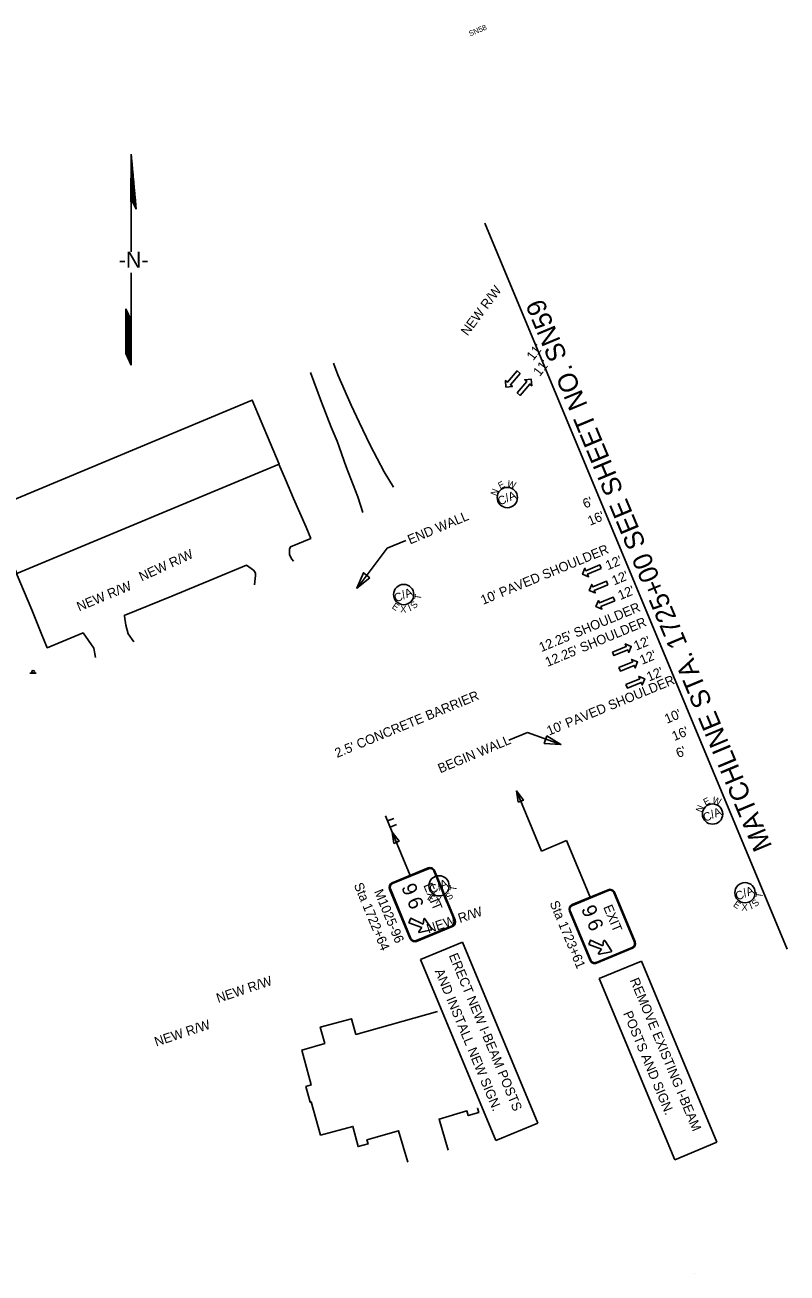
# Model space of a CAD drawing. Extents: x 1817507 to 1819117, y 1191678 to 1192982.
# Drawn here: x 1818554 to 1819117, y 1192060 to 1192982 of the extents above; entities that cross this region are included whole.
import ezdxf

# ---------------------------------------------------------------- set-up
doc = ezdxf.new("R2010")
doc.units = 0
for name, color, linetype in [('RD_EX_Bldg', 7, 'Continuous'), ('RD_EX_Road', 7, 'Continuous'), ('RD_PD_Final_LnLine', 7, 'Continuous'), ('RD_PD_Final_TX', 7, 'Continuous'), ('RD_PD_RW_TX', 7, 'Continuous'), ('RD_SHT_MatchLine', 7, 'Continuous'), ('RD_SHT_TX', 7, 'Continuous'), ('RD_Sketch1', 7, 'Continuous'), ('RD_Sketch10', 7, 'Continuous'), ('RD_Sketch8', 7, 'Continuous'), ('SN_P_Signs', 7, 'Continuous'), ('TERMINATOR', 7, 'Continuous')]:
    doc.layers.add(name, color=color, linetype=linetype)

# ---------------------------------------------------------------- blocks, each defined once
blk = doc.blocks.new('SARRW2')
at = {"layer": 'RD_PD_Final_LnLine'}
blk.add_lwpolyline([(-12, 1.2), (-12, -1.2), (-2.83, -1.2), (-2.83, -2.83), (0, 0), (-2.83, 2.83), (-2.83, 1.2)], close=True, dxfattribs=at)

msp = doc.modelspace()

# ---------------------------------------------------------------- linework, layer by layer
at = {"layer": 'RD_EX_Bldg'}
for points in [[(1818528.67, 1192624.18), (1818548.42, 1192576.83), (1818741.98, 1192657.6), (1818722.22, 1192704.95), (1818528.67, 1192624.18)], [(1818858.93, 1192253.07), (1818798.73, 1192236.03), (1818795.59, 1192247.68), (1818772.38, 1192241.36), (1818775.7, 1192229.45), (1818758.83, 1192224.5), (1818765.81, 1192198.73), (1818761.9, 1192197.58), (1818765.09, 1192185.93), (1818765.77, 1192186.13), (1818772.65, 1192161.62), (1818796.52, 1192168.06), (1818800.36, 1192153.21), (1818807.74, 1192155.14), (1818806.92, 1192158.21), (1818830.19, 1192164.93), (1818837.22, 1192141.71)], [(1818866.99, 1192150.43), (1818860.21, 1192173.56), (1818880.7, 1192179.5), (1818881.72, 1192176.11), (1818889.44, 1192178.26), (1818888.55, 1192181.61), (1818888.62, 1192181.63)]]:
    msp.add_lwpolyline(points, dxfattribs=at)
at = {"layer": 'RD_EX_Road'}
for points in [[(1818765.11, 1192725.26), (1818773.37, 1192703.47), (1818780.54, 1192684.89), (1818784.98, 1192674.59), (1818791.62, 1192655.66), (1818800.21, 1192633.44), (1818803.82, 1192621.97)], [(1818826.57, 1192640.61), (1818819.63, 1192651.9), (1818809.24, 1192671.59), (1818801.13, 1192688.7), (1818795.23, 1192701.24), (1818785.49, 1192723.72), (1818782.1, 1192732.3)], [(1818741.82, 1192657.53), (1818746.67, 1192646.23), (1818752.76, 1192632.23), (1818761.91, 1192610.99), (1818765.38, 1192602.74), (1818750.38, 1192596.5), (1818749.8, 1192594.67), (1818749.6, 1192592.75), (1818749.8, 1192590.83), (1818750.38, 1192589), (1818751.32, 1192587.32), (1818752.59, 1192585.87), (1818752.67, 1192585.79)], [(1818606.51, 1192514.58), (1818605.33, 1192521.69), (1818597.26, 1192532.91), (1818570.76, 1192521.95), (1818566.24, 1192532.56), (1818559.46, 1192549.88), (1818553.27, 1192564.53), (1818547.41, 1192578.46)], [(1818634.79, 1192526.33), (1818630.46, 1192532.18), (1818628.92, 1192538.67), (1818627.77, 1192545.24), (1818627.71, 1192545.67), (1818662.81, 1192560.09), (1818693.01, 1192572.7), (1818717.9, 1192582.91), (1818721.37, 1192580.49), (1818723.16, 1192579.15), (1818724.01, 1192578.06), (1818724.52, 1192576.77), (1818724.65, 1192575.4), (1818724.65, 1192575.4), (1818724.45, 1192573.12), (1818723.89, 1192568.5)]]:
    msp.add_lwpolyline(points, dxfattribs=at)
at = {"layer": 'RD_PD_Final_TX'}
for p, q in [((1818821.86, 1192595.44), (1818799.58, 1192565.95)), ((1818835.58, 1192601.21), (1818821.86, 1192595.44)), ((1818925.47, 1192459.35), (1818911.75, 1192453.58)), ((1818950.19, 1192450.32), (1818925.47, 1192459.35))]:
    msp.add_line(p, q, dxfattribs=at)
at = {"layer": 'RD_SHT_MatchLine'}
msp.add_line((1818894.08, 1192835.81), (1819117.14, 1192299.08), dxfattribs=at)
at = {"layer": 'RD_Sketch1'}
for p, q in [((1818632.84, 1192886.75), (1818632.63, 1192851.59)), ((1818636.56, 1192846.05), (1818632.84, 1192886.75)), ((1818632.84, 1192851.88), (1818632.84, 1192830.06)), ((1818633.14, 1192852.99), (1818636.56, 1192846.05)), ((1818632.84, 1192830.06), (1818632.84, 1192814.59)), ((1818632.84, 1192799.14), (1818632.84, 1192773.37)), ((1818628.84, 1192758.31), (1818628.84, 1192772.48)), ((1818628.84, 1192772.48), (1818632.84, 1192763.92)), ((1818632.84, 1192773.37), (1818632.84, 1192730.85)), ((1818628.84, 1192739.41), (1818628.84, 1192758.31)), ((1818632.84, 1192730.85), (1818628.84, 1192739.41))]:
    msp.add_line(p, q, dxfattribs=at)
for points in [[(1818632.85, 1192852.19), (1818632.85, 1192886.63)], [(1818632.94, 1192852.45), (1818632.94, 1192885.6)], [(1818633.04, 1192852.71), (1818633.04, 1192884.57)], [(1818633.13, 1192852.97), (1818633.13, 1192883.53)], [(1818633.23, 1192852.82), (1818633.23, 1192882.5)], [(1818633.32, 1192852.63), (1818633.32, 1192881.47)], [(1818632.75, 1192851.93), (1818632.75, 1192872.71)], [(1818633.42, 1192852.43), (1818633.42, 1192880.44)], [(1818633.51, 1192852.24), (1818633.51, 1192879.4)], [(1818633.6, 1192852.05), (1818633.6, 1192878.37)], [(1818633.7, 1192851.86), (1818633.7, 1192877.34)], [(1818633.79, 1192851.67), (1818633.79, 1192876.31)], [(1818633.89, 1192851.48), (1818633.89, 1192875.27)], [(1818633.98, 1192851.28), (1818633.98, 1192874.24)], [(1818634.08, 1192851.09), (1818634.08, 1192873.21)], [(1818634.17, 1192850.9), (1818634.17, 1192872.18)], [(1818634.27, 1192850.71), (1818634.27, 1192871.14)], [(1818634.36, 1192850.52), (1818634.36, 1192870.11)], [(1818634.46, 1192850.33), (1818634.46, 1192869.08)], [(1818634.55, 1192850.13), (1818634.55, 1192868.05)], [(1818634.64, 1192849.94), (1818634.64, 1192867.01)], [(1818634.74, 1192849.75), (1818634.74, 1192865.98)], [(1818634.83, 1192849.56), (1818634.83, 1192864.95)], [(1818634.93, 1192849.37), (1818634.93, 1192863.92)], [(1818635.02, 1192849.18), (1818635.02, 1192862.88)], [(1818632.66, 1192851.67), (1818632.66, 1192856.81)], [(1818635.12, 1192848.98), (1818635.12, 1192861.85)], [(1818635.21, 1192848.79), (1818635.21, 1192860.82)], [(1818635.31, 1192848.6), (1818635.31, 1192859.79)], [(1818635.4, 1192848.41), (1818635.4, 1192858.75)], [(1818635.49, 1192848.22), (1818635.49, 1192857.72)], [(1818635.59, 1192848.03), (1818635.59, 1192856.69)], [(1818635.68, 1192847.83), (1818635.68, 1192855.66)], [(1818635.78, 1192847.64), (1818635.78, 1192854.62)], [(1818635.87, 1192847.45), (1818635.87, 1192853.59)], [(1818635.97, 1192847.26), (1818635.97, 1192852.56)], [(1818636.06, 1192847.07), (1818636.06, 1192851.53)], [(1818636.16, 1192846.87), (1818636.16, 1192850.49)], [(1818636.25, 1192846.68), (1818636.25, 1192849.46)], [(1818636.34, 1192846.49), (1818636.34, 1192848.43)], [(1818636.44, 1192846.3), (1818636.44, 1192847.4)], [(1818636.53, 1192846.11), (1818636.53, 1192846.36)], [(1818628.92, 1192739.25), (1818628.92, 1192772.32)], [(1818629.02, 1192739.04), (1818629.02, 1192772.11)], [(1818629.11, 1192738.84), (1818629.11, 1192771.91)], [(1818629.2, 1192738.64), (1818629.2, 1192771.71)], [(1818629.3, 1192738.44), (1818629.3, 1192771.51)], [(1818629.39, 1192738.23), (1818629.39, 1192771.3)], [(1818629.49, 1192738.03), (1818629.49, 1192771.1)], [(1818629.58, 1192737.83), (1818629.58, 1192770.9)], [(1818629.68, 1192737.62), (1818629.68, 1192770.7)], [(1818629.77, 1192737.42), (1818629.77, 1192770.49)], [(1818629.87, 1192737.22), (1818629.87, 1192770.29)], [(1818629.96, 1192737.02), (1818629.96, 1192770.09)], [(1818630.06, 1192736.81), (1818630.06, 1192769.89)], [(1818630.15, 1192736.61), (1818630.15, 1192769.68)], [(1818630.24, 1192736.41), (1818630.24, 1192769.48)], [(1818630.34, 1192736.21), (1818630.34, 1192769.28)], [(1818630.43, 1192736), (1818630.43, 1192769.07)], [(1818630.53, 1192735.8), (1818630.53, 1192768.87)], [(1818630.62, 1192735.6), (1818630.62, 1192768.67)], [(1818630.72, 1192735.4), (1818630.72, 1192768.47)], [(1818630.81, 1192735.19), (1818630.81, 1192768.26)], [(1818630.91, 1192734.99), (1818630.91, 1192768.06)], [(1818631, 1192734.79), (1818631, 1192767.86)], [(1818631.09, 1192734.59), (1818631.09, 1192767.66)], [(1818631.19, 1192734.38), (1818631.19, 1192767.45)], [(1818631.28, 1192734.18), (1818631.28, 1192767.25)], [(1818631.38, 1192733.98), (1818631.38, 1192767.05)], [(1818631.47, 1192733.77), (1818631.47, 1192766.85)], [(1818631.57, 1192733.57), (1818631.57, 1192766.64)], [(1818631.66, 1192733.37), (1818631.66, 1192766.44)], [(1818631.76, 1192733.17), (1818631.76, 1192766.24)], [(1818631.85, 1192732.96), (1818631.85, 1192766.04)], [(1818631.95, 1192732.76), (1818631.95, 1192765.83)], [(1818632.04, 1192732.56), (1818632.04, 1192765.63)], [(1818632.13, 1192732.36), (1818632.13, 1192765.43)], [(1818632.23, 1192732.15), (1818632.23, 1192765.22)], [(1818632.32, 1192731.95), (1818632.32, 1192765.02)], [(1818632.42, 1192731.75), (1818632.42, 1192764.82)], [(1818632.51, 1192731.55), (1818632.51, 1192764.62)], [(1818632.61, 1192731.34), (1818632.61, 1192764.41)], [(1818632.7, 1192731.14), (1818632.7, 1192764.21)], [(1818632.8, 1192730.94), (1818632.8, 1192764.01)]]:
    msp.add_lwpolyline(points, dxfattribs=at)
at = {"layer": 'RD_Sketch10'}
for centre in [(1818910.59, 1192632.9), (1819062.19, 1192398.98)]:
    msp.add_circle(centre, 7.5, dxfattribs=at)
at = {"layer": 'RD_Sketch8'}
for centre in [(1818834.05, 1192561.19), (1818860.15, 1192345.92), (1819086.12, 1192340.84)]:
    msp.add_circle(centre, 7.5, dxfattribs=at)
at = {"layer": 'SN_P_Signs'}
for p, q in [((1818558.07, 1192503.01), (1818562.57, 1192503.01)), ((1818935.88, 1192371.61), (1818917.42, 1192416.02)), ((1818825.61, 1192385.6), (1818820.6, 1192397.65)), ((1818822.18, 1192393.85), (1818826.79, 1192395.76)), ((1818824.11, 1192389.21), (1818828.72, 1192391.13)), ((1818838.91, 1192353.6), (1818825.61, 1192385.6)), ((1818935.88, 1192371.61), (1818954.38, 1192379.3)), ((1818971.74, 1192337.53), (1818954.38, 1192379.3)), ((1818825.61, 1192348.07), (1818852.21, 1192359.12)), ((1818825.84, 1192347.52), (1818852.44, 1192358.57)), ((1818856.36, 1192356.95), (1818871.56, 1192320.38)), ((1818856.91, 1192357.18), (1818872.11, 1192320.61)), ((1818838.87, 1192306.8), (1818823.67, 1192343.37)), ((1818839.42, 1192307.03), (1818824.22, 1192343.6)), ((1818958.44, 1192332), (1818985.04, 1192343.06)), ((1818958.67, 1192331.45), (1818985.27, 1192342.5)), ((1818989.19, 1192340.88), (1819004.39, 1192304.31)), ((1818989.75, 1192341.11), (1819004.94, 1192304.54)), ((1818971.7, 1192290.73), (1818956.5, 1192327.3)), ((1818972.25, 1192290.96), (1818957.06, 1192327.53)), ((1818869.94, 1192316.46), (1818843.34, 1192305.41)), ((1818870.17, 1192315.91), (1818843.57, 1192304.85)), ((1818846.52, 1192291.49), (1818877.56, 1192304.39)), ((1818877.56, 1192304.39), (1818933.21, 1192170.48)), ((1819002.77, 1192300.39), (1818976.17, 1192289.34)), ((1819003, 1192299.84), (1818976.4, 1192288.79)), ((1818902.17, 1192157.58), (1818846.52, 1192291.49)), ((1818978.52, 1192277.42), (1819009.57, 1192290.32)), ((1819009.57, 1192290.32), (1819065.22, 1192156.4)), ((1819034.17, 1192143.5), (1818978.52, 1192277.42)), ((1818933.21, 1192170.48), (1818902.17, 1192157.58)), ((1819065.22, 1192156.4), (1819034.17, 1192143.5)), ((1819048.93, 1192059.7), (1819048.93, 1192059.7))]:
    msp.add_line(p, q, dxfattribs=at)
for points in [[(1818918.68, 1192407.66), (1818917.42, 1192416.02), (1818922.47, 1192409.23)], [(1818826.86, 1192377.24), (1818825.61, 1192385.6), (1818830.65, 1192378.82)]]:
    msp.add_lwpolyline(points, close=True, dxfattribs=at)
for points in [[(1818837.87, 1192318.58), (1818839.24, 1192321.91), (1818848.36, 1192317.66)], [(1818847.33, 1192315.17), (1818837.87, 1192318.58)], [(1818848.36, 1192317.66), (1818848.9, 1192321.3)], [(1818849.72, 1192321.48), (1818854.73, 1192313.97)], [(1818845.15, 1192312.21), (1818847.33, 1192315.17)], [(1818854.45, 1192313.28), (1818845.6, 1192311.5)], [(1818970.7, 1192302.52), (1818972.07, 1192305.84), (1818981.19, 1192301.59)], [(1818980.16, 1192299.1), (1818970.7, 1192302.52)], [(1818981.19, 1192301.59), (1818981.73, 1192305.23)], [(1818982.55, 1192305.41), (1818987.57, 1192297.9)], [(1818977.98, 1192296.14), (1818980.16, 1192299.1)], [(1818987.28, 1192297.21), (1818978.43, 1192295.43)]]:
    msp.add_lwpolyline(points, dxfattribs=at)
msp.add_circle((1818560.33, 1192504.02), 1, dxfattribs=at)
for centre, radius, start, end in [((1818853.59, 1192355.8), 3.6, 22.56659, 112.56659), ((1818853.59, 1192355.8), 3, 22.56659, 112.56659), ((1818826.99, 1192344.75), 3.6, 112.56659, 202.56659), ((1818826.99, 1192344.75), 3, 112.56659, 202.56659), ((1818986.42, 1192339.73), 3.6, 22.56659, 112.56659), ((1818986.42, 1192339.73), 3, 22.56659, 112.56659), ((1818959.83, 1192328.68), 3.6, 112.56659, 202.56659), ((1818959.83, 1192328.68), 3, 112.56659, 202.56659), ((1818849.34, 1192321.23), 0.45, 33.74449, 171.52869), ((1818868.79, 1192319.23), 3, 292.56659, 22.56659), ((1818868.79, 1192319.23), 3.6, 292.56659, 22.56659), ((1818845.51, 1192311.94), 0.45, 143.60449, 281.38869), ((1818854.36, 1192313.72), 0.45, 281.38869, 33.74449), ((1818842.19, 1192308.18), 3.6, 202.56659, 292.56659), ((1818842.19, 1192308.18), 3, 202.56659, 292.56659), ((1818982.18, 1192305.16), 0.45, 33.74449, 171.52869), ((1819001.62, 1192303.16), 3, 292.56659, 22.56659), ((1819001.62, 1192303.16), 3.6, 292.56659, 22.56659), ((1818975.02, 1192292.11), 3.6, 202.56659, 292.56659), ((1818975.02, 1192292.11), 3, 202.56659, 292.56659), ((1818978.34, 1192295.87), 0.45, 143.60449, 281.38869), ((1818987.19, 1192297.65), 0.45, 281.38869, 33.74449)]:
    msp.add_arc(centre, radius, start, end, dxfattribs=at)
at = {"layer": 'TERMINATOR'}
for points in [[(1818809.13, 1192573.69), (1818799.52, 1192565.91), (1818804.34, 1192577.3)], [(1818939.71, 1192456.89), (1818950.19, 1192450.32), (1818937.85, 1192451.18)]]:
    msp.add_lwpolyline(points, close=True, dxfattribs=at)

# ---------------------------------------------------------------- block references
at = {"layer": 'RD_PD_Final_LnLine'}
for p, xscale, yscale, rotation in [((1818909.57, 1192714.62), 1.2000000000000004, 1.2000000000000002, -130.58005673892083), ((1818928.29, 1192720.33), 1.2000000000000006, 1.2000000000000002, 49.41994326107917), ((1818966.1, 1192576.22), 1.2000000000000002, 1.2000000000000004, -157.44760385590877), ((1818971.06, 1192564.28), 1.2000000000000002, 1.2000000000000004, -157.44760385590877), ((1818976.02, 1192552.34), 1.2000000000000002, 1.2000000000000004, -157.44760385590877), ((1819002.08, 1192522.9), 1.2000000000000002, 1.2000000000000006, 22.552396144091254), ((1819006.84, 1192511.46), 1.2000000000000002, 1.2000000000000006, 22.552396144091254), ((1819012.06, 1192498.9), 1.2000000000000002, 1.2000000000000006, 22.552396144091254)]:
    msp.add_blockref('SARRW2', p, dxfattribs=dict(at, xscale=xscale, yscale=yscale, rotation=rotation))

# ---------------------------------------------------------------- texts
at = {"layer": 'RD_PD_Final_TX'}
for s, rotation, p in [("11'", 52.63676, (1818929.68, 1192733.62)), ("11'", 52.63676, (1818934.54, 1192721.93)), ("6'", 22.75903, (1818968.02, 1192624.71)), ("16'", 22.75903, (1818971.69, 1192612)), ('END WALL', 22.81659, (1818838.72, 1192598.16)), ("10' PAVED SHOULDER", 22.4268, (1818892.66, 1192553.54)), ("12'", 22.75903, (1818984.84, 1192579.14)), ("12'", 22.75903, (1818989.49, 1192567.94)), ("12'", 22.75903, (1818994.02, 1192557.05)), ("12.25' SHOULDER", 22.56659, (1818935.75, 1192518.62)), ("12.25' SHOULDER", 22.56659, (1818940.29, 1192507.7)), ("12'", 22.75903, (1819005.74, 1192519.71)), ("12'", 22.75903, (1819010.1, 1192509.23)), ("12'", 22.75903, (1819015.24, 1192496.85)), ("10' PAVED SHOULDER", 22.4268, (1818941.41, 1192456.89)), ("2.5' CONCRETE BARRIER", 22.4268, (1818784.89, 1192440.45)), ("10'", 22.75903, (1819028.45, 1192465.66)), ("16'", 22.75903, (1819033.88, 1192452.87)), ('BEGIN WALL', 22.81659, (1818861.09, 1192429.01)), ("6'", 22.75903, (1819036.89, 1192440.32))]:
    msp.add_text(s, height=7, rotation=rotation, dxfattribs=at).set_placement(p)
at = {"layer": 'RD_PD_RW_TX'}
for rotation, p in [(53.41904, (1818881.25, 1192751.99)), (24.71535, (1818640.57, 1192570.81)), (22.56659, (1818594.36, 1192548.69)), (18.36998, (1818852.32, 1192310.65)), (18.36998, (1818697.05, 1192259.35)), (18.36998, (1818651.34, 1192227.1))]:
    msp.add_text('NEW R/W', height=7, rotation=rotation, dxfattribs=at).set_placement(p)
at = {"layer": 'RD_SHT_TX'}
for s, height, rotation, p in [('SN58', 4, 22.56659, (1818883.05, 1192973.72)), ('MATCHLINE STA. 1725+00 SEE SHEET NO. SN59', 14.1726, 112.67894, (1819106.35, 1192375.11))]:
    msp.add_text(s, height=height, rotation=rotation, dxfattribs=at).set_placement(p)
at = {"layer": 'RD_Sketch1'}
msp.add_text('-N-', height=11.811, rotation=0, dxfattribs=at).set_placement((1818623.64, 1192802.85))
at = {"layer": 'RD_Sketch10'}
for s, height, rotation, p in [('E', 5, 26.89964, (1818905.26, 1192639.03)), ('W', 5, 341.8692, (1818909.95, 1192641.25)), ('N', 5, 67.43636, (1818902.54, 1192633.71)), ('C/A', 6.25, 22.56659, (1818905, 1192627.03)), ('E', 5, 26.89964, (1819056.86, 1192405.11)), ('W', 5, 341.8692, (1819061.55, 1192407.33)), ('N', 5, 67.43636, (1819054.14, 1192399.79)), ('C/A', 6.25, 22.56659, (1819056.6, 1192393.11))]:
    msp.add_text(s, height=height, rotation=rotation, dxfattribs=at).set_placement(p)
at = {"layer": 'RD_Sketch8'}
for s, height, rotation, p in [('C/A', 6.25, 22.56659, (1818828.47, 1192555.32)), ('T', 5, 80.75173, (1818846.81, 1192557.06)), ('E', 5, 325.77783, (1818824.89, 1192551.4)), ('X', 5, 358.2072, (1818831.47, 1192548.01)), ('I', 5, 22.3672, (1818838.53, 1192548.7)), ('S', 5, 44.35903, (1818841.83, 1192550.26)), ('C/A', 6.25, 22.56659, (1818854.56, 1192340.05)), ('T', 5, 80.75173, (1818872.9, 1192341.79)), ('E', 5, 325.77783, (1818850.98, 1192336.13)), ('X', 5, 358.2072, (1818857.56, 1192332.74)), ('I', 5, 22.3672, (1818864.62, 1192333.43)), ('S', 5, 44.35903, (1818867.93, 1192335)), ('C/A', 6.25, 22.56659, (1819080.54, 1192334.97)), ('T', 5, 80.75173, (1819098.88, 1192336.71)), ('E', 5, 325.77783, (1819076.96, 1192331.05)), ('X', 5, 358.2072, (1819083.54, 1192327.66)), ('I', 5, 22.3672, (1819090.6, 1192328.35)), ('S', 5, 44.35903, (1819093.9, 1192329.91))]:
    msp.add_text(s, height=height, rotation=rotation, dxfattribs=at).set_placement(p)
at = {"layer": 'SN_P_Signs'}
for s, height, rotation, p in [('Sta 1722+64', 7, 292.56667, (1818797.09, 1192346.57)), ('9', 10.8, 292.56659, (1818832.07, 1192345.04)), ('EXIT', 7, 292.56659, (1818848.44, 1192346.29)), ('M1025-96', 7, 292.56667, (1818811.99, 1192341.72)), ('6', 10.8, 292.56659, (1818836.26, 1192334.96)), ('Sta 1723+61', 7, 292.56667, (1818941.67, 1192333.23)), ('9', 10.8, 292.56659, (1818964.9, 1192328.98)), ('EXIT', 7, 292.56659, (1818981.28, 1192330.22)), ('6', 10.8, 292.56659, (1818969.09, 1192318.89)), ('ERECT NEW I-BEAM POSTS', 6.9998, 292.56667, (1818867.23, 1192294.43)), ('AND INSTALL NEW SIGN.', 6.9998, 292.56667, (1818856.87, 1192282.88)), ('REMOVE EXISTING I-BEAM', 6.9998, 292.56667, (1819000.97, 1192276.19)), ('POSTS AND SIGN.', 6.9998, 292.56667, (1818995.99, 1192251.69))]:
    msp.add_text(s, height=height, rotation=rotation, dxfattribs=at).set_placement(p)

doc.saveas('drawing.dxf')
